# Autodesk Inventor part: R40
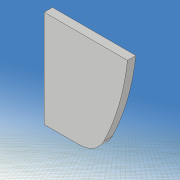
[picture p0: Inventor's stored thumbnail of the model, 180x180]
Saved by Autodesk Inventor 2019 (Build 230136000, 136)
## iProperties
Created: 2021-05
Part Number: R40
Material: 一般
Document SubType Name: Modeling
Designer: kikut
Density: 1 g/cm^3
Appearance: 既定
Mass: 0.05042 g
Surface Area: 1.90077 cm^2
Volume: 0.05042 cm^3
Author: kikut
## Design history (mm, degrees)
sketch "スケッチ1"
  geometry: L1 (80, 60)-(-80, 60); L2 (-80, 60)-(-80, -60); L3 (-80, -60)-(80, -60); L4 (80, -60)-(80, 60); L5 (80, 60)-(-80, -60); L6 (-80, 60)-(80, -60); 1 further point
  constraints: 12 end point, 2 midpoint, 2 parallel, 1 horizontal, 1 perpendicular
  dimensions: "d0" = 160 distance of L2.end L3.end; "d1" = 120 distance of L1.end L2.end
extrude "押し出し1" new body sketch "スケッチ1" stored distance "d2" = 0.6; taper "d3" = 0 deg
sketch "スケッチ2"
  geometry: L1 (-140, 0)-(140, 0) reference; L2 (0, -54)-(20, -30); L3 (0, 54)-(20, 30); L4 (0, -3)-(6.514, -3); L5 (6.514, -3)-(16, -6); L6 (16, -6)-(24, -3); L7 (24, -3)-(33.716, -3); L8 (0, 3)-(6.514, 3); L9 (6.514, 3)-(16, 6); L10 (16, 6)-(24, 3); L11 (24, 3)-(33.716, 3); L12 (0, -98)-(0, 98) reference; L13 (-100, -70)-(100, -70); L14 (100, -70)-(100, 70); L15 (100, 70)-(-100, 70); L16 (-100, 70)-(-100, -70); L17 (-100, -70)-(100, 70); L18 (100, -70)-(-100, 70); A1 r 60 centre (54.312, 28.5) between (0, 54) and (0, 3); A2 r 60 centre (54.312, -28.5) between (0, -3) and (0, -54); A3 r 18.111 centre (18, -12) between (20, -30) and (33.716, -3); A4 r 18.111 centre (18, 12) between (33.716, 3) and (20, 30); 1 further point
  constraints: 32 end point, 8 point on circle, 8 symmetric about line, 4 centre point, 3 horizontal, 2 collinear, 2 midpoint, 2 parallel, 1 perpendicular
  dimensions: "d5" = 60 radius of A1; "d6" = 6 distance of L8.start L4.start; "d7" = 108 distance of L3.start L2.start; "d8" = 0 horizontal distance of L3.start L8.start; "d9" = 60 distance of L3.end L2.end; "d10" = 0 horizontal distance of point (0, 0) L3.start; "d11" = 20 horizontal distance of L3.start L3.end; "d12" = 24 distance of A4.centre A3.centre; "d13" = 6 distance of L11.end L7.end; "d14" = 12 distance of L9.end L5.end; "d15" = 16 distance from line of L12 L5.end; "d16" = 24 distance from line of L6.end L12; "d17" = 200 distance of L14.end L15.end; "d18" = 140 distance of L15.end L13.start; "d30" = 18 distance from line of L12 A4.centre
extrude "押し出し2" cut sketch "スケッチ2" stored distance "d19" = 10; taper "d20" = 0 deg
sketch "スケッチ3"
  geometry: L1 (49.705, -17.97)-(33.948, -15.191); L2 (33.948, -15.191)-(34.295, -13.222); L3 (34.295, -13.222)-(50.052, -16); L4 (50.052, -16)-(49.705, -17.97); L5 (49.705, -17.97)-(34.295, -13.222); L6 (33.948, -15.191)-(50.052, -16); L7 (50.052, 16)-(34.295, 13.222); L8 (34.295, 13.222)-(33.948, 15.191); L9 (33.948, 15.191)-(49.705, 17.97); L10 (49.705, 17.97)-(50.052, 16); L11 (50.052, 16)-(33.948, 15.191); L12 (34.295, 13.222)-(49.705, 17.97); L13 (-112, 0)-(112, 0) reference; L14 (0, -84)-(0, 84) reference; 3 further points
  constraints: 24 end point, 4 midpoint, 4 parallel, 2 perpendicular, 2 symmetric about line
  dimensions: "d21" = 2 distance of L3.end L1.start; "d22" = 2 distance of L9.end L7.start; "d23" = 16 distance of L8.end L9.end; "d24" = 42 distance from line of L14 point (42, 15.596); "d26" = 10 deg angle of L7 L13; "d62" = 16 distance from line of L3.end L13
extrude "押し出し3" join sketch "スケッチ3" distance "d27" = 0.6; taper "d28" = 0 deg
fillet "フィレット1" dims "d31" = 2
fillet "フィレット2" dims "d32" = 1
sketch "スケッチ6"
  geometry: L1 (-20, 60)-(80, 60); L2 (80, 60)-(80, -60); L3 (80, -60)-(-20, -60); L4 (-20, -60)-(-20, 60); L5 (-46.168, 0)-(93.832, 0) reference; L6 (0, -84)-(0, 84) reference; L7 (30, 0)-(36, 0); L8 (36, 0)-(36, 10); L9 (36, 10)-(30, 10); L10 (30, 10)-(30, 0); 1 further point
  constraints: 16 end point, 4 parallel, 2 horizontal, 2 perpendicular, 1 other
  dimensions: "d63" = 120 distance of L3.end L1.start; "d64" = 100 distance of L1.start L1.end; "d65" = 20 distance between parallel lines of L6 L4; "d66" = 6 distance of L8.end L9.end; "d73" = 10 distance of L9.end L7.start; "d74" = 0 distance between parallel lines of L7 L5; "d75" = 50 distance between parallel lines of L10 L4
extrude "押し出し4" cut sketch "スケッチ6" stored distance "d70" = 10; taper "d71" = 0 deg
node "ソリッド1"
